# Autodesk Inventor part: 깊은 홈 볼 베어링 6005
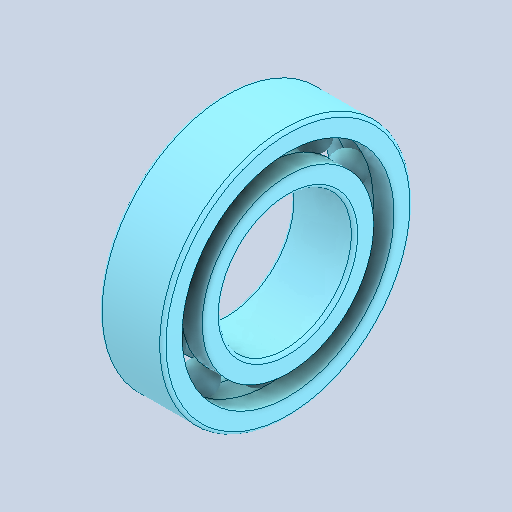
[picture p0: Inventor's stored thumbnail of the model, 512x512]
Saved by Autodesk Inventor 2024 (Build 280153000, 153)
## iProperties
Created: 2025-11
Part Number: 깊은 홈 볼 베어링 6005
Material: 강철, 연강
Description: 깊은 그루브 볼 베어링
Document SubType Name: Modeling
Designer: Eud07
Density: 7.85 g/cm^3
Appearance: 기본값
Author: jhkim
Sending System: Autodesk Inventor 2026
Preprocessor: ST-DEVELOPER v20.1
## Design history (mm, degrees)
node "깊은 홈 볼 베어링 60051"
node "솔리드1"
node "솔리드2"
node "솔리드3"
node "솔리드4"
node "솔리드5"
node "솔리드6"
node "솔리드7"
node "솔리드8"
node "솔리드9"
node "솔리드10"
node "솔리드11"
node "솔리드12"
body "Solid1"
node "Solid1:1"
node "Solid1:2"
node "Solid1:3"
node "Solid1:4"
node "Solid1:5"
node "Solid1:6"
node "Solid1:7"
node "Solid1:8"
node "Solid1:9"
node "Solid1:10"
node "Solid1:11"
